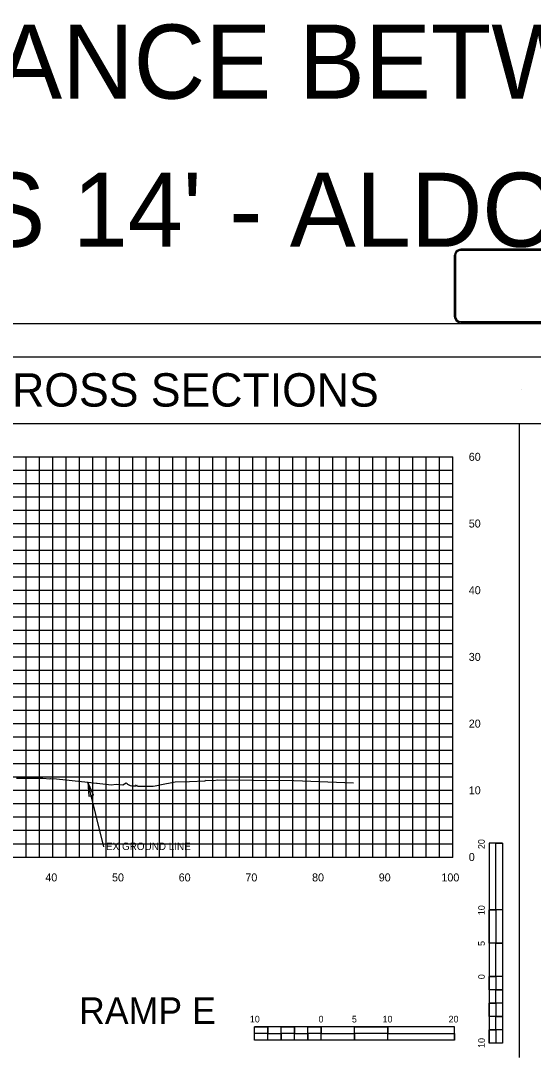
# Model space of a CAD drawing. Extents: x 2193008 to 2198143, y 1236112 to 1237864.
# Drawn here: x 2195304 to 2195380.9, y 1237228.8 to 1237383.5 of the extents above; entities that cross this region are included whole.
import ezdxf

# ---------------------------------------------------------------- set-up
doc = ezdxf.new("R2010")
doc.units = 0
for name, color, linetype in [('3', 7, 'Continuous'), ('31', 7, 'Continuous'), ('60', 7, 'Continuous'), ('ANNO-SHT', 7, 'Continuous'), ('DRAINAGE', 7, 'Continuous'), ('GSDIMS', 7, 'Continuous'), ('GSOUTLINE', 7, 'Continuous'), ('Level 1', 7, 'Continuous'), ('Level 33', 7, 'Continuous'), ('Level 55', 7, 'Continuous'), ('LIMT-CSLINE', 7, 'Continuous'), ('M-ROADS', 7, 'Continuous'), ('SHT-BNDRY', 7, 'Continuous')]:
    doc.layers.add(name, color=color, linetype=linetype)

# ---------------------------------------------------------------- blocks, each defined once
blk = doc.blocks.new('SC47208')
at = {"layer": 'Level 1'}
blk.add_line((0, 0), (0, 0), dxfattribs=at)

msp = doc.modelspace()

# ---------------------------------------------------------------- linework, layer by layer
msp.add_lwpolyline([(2195228.78, 1237133.05), (2195528.78, 1237133.05), (2195528.78, 1237323.05), (2195228.78, 1237323.05)], close=True)
at = {"layer": '3'}
for p, q in [((2195378.78, 1237228.05), (2195378.78, 1237323.05)), ((2195316.45, 1237259.66), (2195314.05, 1237269.34))]:
    msp.add_line(p, q, dxfattribs=at)
at = {"layer": '60'}
for p, q in [((2195368.78, 1237258.11), (2195368.78, 1237318.11)), ((2195368.84, 1237298.11), (2195368.78, 1237298.11)), ((2195368.84, 1237288.11), (2195368.78, 1237288.11)), ((2195368.84, 1237278.11), (2195368.78, 1237278.11)), ((2195368.84, 1237268.11), (2195368.78, 1237268.11)), ((2195238.78, 1237258.11), (2195368.78, 1237258.11)), ((2195308.78, 1237258.05), (2195308.78, 1237258.11)), ((2195318.78, 1237258.05), (2195318.78, 1237258.11)), ((2195328.78, 1237258.05), (2195328.78, 1237258.11)), ((2195338.78, 1237258.05), (2195338.78, 1237258.11)), ((2195348.78, 1237258.05), (2195348.78, 1237258.11)), ((2195358.78, 1237258.05), (2195358.78, 1237258.11)), ((2195368.78, 1237258.05), (2195368.78, 1237258.11)), ((2195368.84, 1237258.11), (2195368.78, 1237258.11))]:
    msp.add_line(p, q, dxfattribs=at)
at = {"layer": 'GSDIMS'}
msp.add_lwpolyline([(2195314.05, 1237269.34), (2195314.22, 1237267.21), (2195314.9, 1237267.39)], close=True, dxfattribs=at)
at = {"layer": 'GSOUTLINE'}
for p, q in [((2195369, 1237348.22), (2195369, 1237339.22)), ((2195369.17, 1237348.22), (2195369.17, 1237339.22)), ((2195389.5, 1237349.22), (2195370, 1237349.22)), ((2195389.5, 1237349.05), (2195370, 1237349.05)), ((2195370, 1237338.39), (2195389.5, 1237338.39)), ((2195370, 1237338.22), (2195389.5, 1237338.22))]:
    msp.add_line(p, q, dxfattribs=at)
for centre, major_axis, start_param, end_param in [((2195370, 1237348.22), (1, 0), 1.570796, 3.141593), ((2195370, 1237348.22), (0.833, 0), 1.570796, 3.141593), ((2195370, 1237339.22), (1, 0), 3.141593, 4.712389), ((2195370, 1237339.22), (0.833, 0), 3.141593, 4.712389)]:
    msp.add_ellipse(centre, major_axis=major_axis, ratio=0.999829, start_param=start_param, end_param=end_param, dxfattribs=at)
at = {"layer": 'Level 1'}
for p, q in [((2195374.26, 1237260.19), (2195374.26, 1237230.19)), ((2195376.26, 1237260.19), (2195374.26, 1237260.19)), ((2195376.26, 1237260.19), (2195376.26, 1237250.19)), ((2195376.26, 1237260.19), (2195376.26, 1237230.19)), ((2195375.26, 1237250.19), (2195374.26, 1237250.19)), ((2195376.26, 1237250.19), (2195374.26, 1237250.19)), ((2195375.26, 1237250.19), (2195375.26, 1237245.19)), ((2195376.26, 1237245.19), (2195374.26, 1237245.19)), ((2195376.26, 1237245.19), (2195375.26, 1237245.19)), ((2195376.26, 1237245.19), (2195376.26, 1237240.19)), ((2195375.26, 1237240.19), (2195374.26, 1237240.19)), ((2195376.26, 1237240.19), (2195374.26, 1237240.19)), ((2195375.26, 1237240.19), (2195375.26, 1237238.19)), ((2195376.26, 1237238.19), (2195375.26, 1237238.19)), ((2195376.26, 1237238.19), (2195376.26, 1237236.19)), ((2195375.26, 1237236.19), (2195374.26, 1237236.19)), ((2195375.26, 1237236.19), (2195375.26, 1237234.19)), ((2195376.26, 1237234.19), (2195375.26, 1237234.19)), ((2195376.26, 1237234.19), (2195376.26, 1237232.19)), ((2195369.05, 1237232.63), (2195339.05, 1237232.63)), ((2195339.05, 1237230.63), (2195339.05, 1237232.63)), ((2195341.05, 1237231.63), (2195341.05, 1237232.63)), ((2195345.05, 1237231.63), (2195345.05, 1237232.63)), ((2195349.05, 1237231.63), (2195349.05, 1237232.63)), ((2195349.05, 1237230.63), (2195349.05, 1237232.63)), ((2195354.05, 1237230.63), (2195354.05, 1237232.63)), ((2195359.05, 1237231.63), (2195359.05, 1237232.63)), ((2195359.05, 1237230.63), (2195359.05, 1237232.63)), ((2195369.05, 1237230.63), (2195369.05, 1237232.63)), ((2195375.26, 1237232.19), (2195374.26, 1237232.19)), ((2195375.26, 1237232.19), (2195375.26, 1237230.19)), ((2195341.05, 1237231.63), (2195339.05, 1237231.63)), ((2195369.05, 1237230.63), (2195339.05, 1237230.63)), ((2195343.05, 1237230.63), (2195341.05, 1237230.63)), ((2195343.05, 1237230.63), (2195343.05, 1237231.63)), ((2195345.05, 1237231.63), (2195343.05, 1237231.63)), ((2195347.05, 1237230.63), (2195345.05, 1237230.63)), ((2195347.05, 1237230.63), (2195347.05, 1237231.63)), ((2195349.05, 1237231.63), (2195347.05, 1237231.63)), ((2195354.05, 1237230.63), (2195349.05, 1237230.63)), ((2195354.05, 1237230.63), (2195354.05, 1237231.63)), ((2195359.05, 1237231.63), (2195354.05, 1237231.63)), ((2195369.05, 1237230.63), (2195359.05, 1237230.63)), ((2195376.26, 1237230.19), (2195374.26, 1237230.19))]:
    msp.add_line(p, q, dxfattribs=at)
for points in [[(2195375.26, 1237250.19), (2195375.26, 1237260.19), (2195376.26, 1237260.19), (2195376.26, 1237250.19)], [(2195374.26, 1237245.19), (2195374.26, 1237250.19), (2195375.26, 1237250.19), (2195375.26, 1237245.19)], [(2195375.26, 1237240.19), (2195375.26, 1237245.19), (2195376.26, 1237245.19), (2195376.26, 1237240.19)], [(2195374.26, 1237238.19), (2195374.26, 1237240.19), (2195375.26, 1237240.19), (2195375.26, 1237238.19)], [(2195375.26, 1237236.19), (2195375.26, 1237238.19), (2195376.26, 1237238.19), (2195376.26, 1237236.19)], [(2195374.26, 1237234.19), (2195374.26, 1237236.19), (2195375.26, 1237236.19), (2195375.26, 1237234.19)], [(2195375.26, 1237232.19), (2195375.26, 1237234.19), (2195376.26, 1237234.19), (2195376.26, 1237232.19)], [(2195339.05, 1237232.63), (2195341.05, 1237232.63), (2195341.05, 1237231.63), (2195339.05, 1237231.63)], [(2195343.05, 1237232.63), (2195345.05, 1237232.63), (2195345.05, 1237231.63), (2195343.05, 1237231.63)], [(2195347.05, 1237232.63), (2195349.05, 1237232.63), (2195349.05, 1237231.63), (2195347.05, 1237231.63)], [(2195354.05, 1237232.63), (2195359.05, 1237232.63), (2195359.05, 1237231.63), (2195354.05, 1237231.63)], [(2195374.26, 1237230.19), (2195374.26, 1237232.19), (2195375.26, 1237232.19), (2195375.26, 1237230.19)], [(2195341.05, 1237231.63), (2195343.05, 1237231.63), (2195343.05, 1237230.63), (2195341.05, 1237230.63)], [(2195345.05, 1237231.63), (2195347.05, 1237231.63), (2195347.05, 1237230.63), (2195345.05, 1237230.63)], [(2195349.05, 1237231.63), (2195354.05, 1237231.63), (2195354.05, 1237230.63), (2195349.05, 1237230.63)], [(2195359.05, 1237231.63), (2195369.05, 1237231.63), (2195369.05, 1237230.63), (2195359.05, 1237230.63)]]:
    msp.add_lwpolyline(points, close=True, dxfattribs=at)
at = {"layer": 'M-ROADS'}
for p, q in [((2195238.78, 1237318.11), (2195368.78, 1237318.11)), ((2195304.78, 1237258.11), (2195304.78, 1237318.11)), ((2195306.78, 1237258.11), (2195306.78, 1237318.11)), ((2195308.78, 1237258.11), (2195308.78, 1237318.11)), ((2195310.78, 1237258.11), (2195310.78, 1237318.11)), ((2195312.78, 1237258.11), (2195312.78, 1237318.11)), ((2195314.78, 1237258.11), (2195314.78, 1237318.11)), ((2195316.78, 1237258.11), (2195316.78, 1237318.11)), ((2195318.78, 1237258.11), (2195318.78, 1237318.11)), ((2195320.78, 1237258.11), (2195320.78, 1237318.11)), ((2195322.78, 1237258.11), (2195322.78, 1237318.11)), ((2195324.78, 1237258.11), (2195324.78, 1237318.11)), ((2195326.78, 1237258.11), (2195326.78, 1237318.11)), ((2195328.78, 1237258.11), (2195328.78, 1237318.11)), ((2195330.78, 1237258.11), (2195330.78, 1237318.11)), ((2195332.78, 1237258.11), (2195332.78, 1237318.11)), ((2195334.78, 1237258.11), (2195334.78, 1237318.11)), ((2195336.78, 1237258.11), (2195336.78, 1237318.11)), ((2195338.78, 1237258.11), (2195338.78, 1237318.11)), ((2195340.78, 1237258.11), (2195340.78, 1237318.11)), ((2195342.78, 1237258.11), (2195342.78, 1237318.11)), ((2195344.78, 1237258.11), (2195344.78, 1237318.11)), ((2195346.78, 1237258.11), (2195346.78, 1237318.11)), ((2195348.78, 1237258.11), (2195348.78, 1237318.11)), ((2195350.78, 1237258.11), (2195350.78, 1237318.11)), ((2195352.78, 1237258.11), (2195352.78, 1237318.11)), ((2195354.78, 1237258.11), (2195354.78, 1237318.11)), ((2195356.78, 1237258.11), (2195356.78, 1237318.11)), ((2195358.78, 1237258.11), (2195358.78, 1237318.11)), ((2195360.78, 1237258.11), (2195360.78, 1237318.11)), ((2195362.78, 1237258.11), (2195362.78, 1237318.11)), ((2195364.78, 1237258.11), (2195364.78, 1237318.11)), ((2195366.78, 1237258.11), (2195366.78, 1237318.11)), ((2195368.78, 1237258.11), (2195368.78, 1237318.11)), ((2195238.78, 1237316.11), (2195368.78, 1237316.11)), ((2195238.78, 1237314.11), (2195368.78, 1237314.11)), ((2195238.78, 1237312.11), (2195368.78, 1237312.11)), ((2195238.78, 1237310.11), (2195368.78, 1237310.11)), ((2195238.78, 1237308.11), (2195368.78, 1237308.11)), ((2195238.78, 1237306.11), (2195368.78, 1237306.11)), ((2195238.78, 1237304.11), (2195368.78, 1237304.11)), ((2195238.78, 1237302.11), (2195368.78, 1237302.11)), ((2195238.78, 1237300.11), (2195368.78, 1237300.11)), ((2195238.78, 1237298.11), (2195368.78, 1237298.11)), ((2195238.78, 1237296.11), (2195368.78, 1237296.11)), ((2195238.78, 1237294.11), (2195368.78, 1237294.11)), ((2195238.78, 1237292.11), (2195368.78, 1237292.11)), ((2195238.78, 1237290.11), (2195368.78, 1237290.11)), ((2195238.78, 1237288.11), (2195368.78, 1237288.11)), ((2195238.78, 1237286.11), (2195368.78, 1237286.11)), ((2195238.78, 1237284.11), (2195368.78, 1237284.11)), ((2195238.78, 1237282.11), (2195368.78, 1237282.11)), ((2195238.78, 1237280.11), (2195368.78, 1237280.11)), ((2195238.78, 1237278.11), (2195368.78, 1237278.11)), ((2195238.78, 1237276.11), (2195368.78, 1237276.11)), ((2195238.78, 1237274.11), (2195368.78, 1237274.11)), ((2195238.78, 1237272.11), (2195368.78, 1237272.11)), ((2195238.78, 1237270.11), (2195368.78, 1237270.11)), ((2195238.78, 1237268.11), (2195368.78, 1237268.11)), ((2195238.78, 1237266.11), (2195368.78, 1237266.11)), ((2195238.78, 1237264.11), (2195368.78, 1237264.11)), ((2195238.78, 1237262.11), (2195368.78, 1237262.11)), ((2195238.78, 1237260.11), (2195368.78, 1237260.11)), ((2195238.78, 1237258.11), (2195368.78, 1237258.11))]:
    msp.add_line(p, q, dxfattribs=at)
msp.add_lwpolyline([(2195203.79, 1237118.04), (2195543.79, 1237118.04), (2195543.79, 1237338.04), (2195203.79, 1237338.04)], close=True, dxfattribs=at)
msp.add_lwpolyline([(2195303.34, 1237269.95), (2195304.19, 1237269.94), (2195305.98, 1237269.92), (2195306.81, 1237269.93), (2195307.3, 1237269.92), (2195308.34, 1237269.83), (2195308.5, 1237269.87), (2195309.34, 1237269.84), (2195314.05, 1237269.34), (2195315.35, 1237269.19), (2195315.45, 1237269.19), (2195317.54, 1237268.94), (2195318.28, 1237269.02), (2195319.31, 1237268.94), (2195319.78, 1237269.24), (2195319.97, 1237269.12), (2195320.02, 1237269.03), (2195320.38, 1237268.81), (2195320.65, 1237268.78), (2195321.25, 1237268.77), (2195321.26, 1237268.77), (2195321.26, 1237268.78), (2195321.37, 1237268.94), (2195321.41, 1237268.78), (2195321.57, 1237268.74), (2195322.15, 1237268.74), (2195323.85, 1237268.74), (2195324.69, 1237268.9), (2195324.83, 1237268.92), (2195327.17, 1237269.39), (2195329.31, 1237269.44), (2195331.63, 1237269.52), (2195331.7, 1237269.62), (2195332.92, 1237269.6), (2195333.56, 1237269.69), (2195338.88, 1237269.62), (2195344.94, 1237269.56), (2195353.88, 1237269.22)], dxfattribs=at)
at = {"layer": 'SHT-BNDRY'}
msp.add_lwpolyline([(2195216.29, 1237123.04), (2195538.79, 1237123.04), (2195538.79, 1237333.04), (2195216.29, 1237333.04)], close=True, dxfattribs=at)

# ---------------------------------------------------------------- block references
at = {"layer": 'DRAINAGE', "xscale": 0.20000000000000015, "yscale": 0.20000000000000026, "rotation": -116.41666666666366}
msp.add_blockref('SC47208', (2195379.1, 1237328.23), dxfattribs=at)
msp.add_blockref('SC47208', (2195379.1, 1237328.23), dxfattribs=at)

# ---------------------------------------------------------------- texts
at = {"layer": '31'}
for s, p in [('60', (2195371.18, 1237317.51)), ('50', (2195371.18, 1237307.51)), ('40', (2195371.18, 1237297.51)), ('30', (2195371.18, 1237287.51)), ('20', (2195371.18, 1237277.51)), ('10', (2195371.18, 1237267.51)), ('0', (2195371.18, 1237257.51))]:
    msp.add_text(s, height=1.2, dxfattribs=at).set_placement(p)
at = {"layer": 'ANNO-SHT'}
msp.add_text('              SIGN CROSS SECTIONS               ', height=4.9995, rotation=360, dxfattribs=at).set_placement((2195253.66, 1237325.64))
at = {"layer": 'Level 1'}
for s, height, rotation, p in [('20', 0.999, 90.0572, (2195373.58, 1237259.3)), ('10', 0.999, 90.0572, (2195373.58, 1237249.39)), ('5', 1, 90.0572, (2195373.58, 1237244.78)), ('0', 1, 90.0572, (2195373.58, 1237239.79)), ('10', 0.999, 0.0572, (2195338.35, 1237233.3)), ('0', 1, 0.0572, (2195348.65, 1237233.3)), ('5', 0.999, 0.0572, (2195353.65, 1237233.3)), ('10', 0.999, 0.0572, (2195358.25, 1237233.3)), ('20', 0.999, 0.0572, (2195368.15, 1237233.3)), ('10', 0.999, 90.0572, (2195373.58, 1237229.49))]:
    msp.add_text(s, height=height, rotation=rotation, dxfattribs=at).set_placement(p)
at = {"layer": 'Level 33'}
msp.add_text('RAMP E', height=3.998, rotation=360, dxfattribs=at).set_placement((2195312.74, 1237233.07))
at = {"layer": 'Level 55'}
for s, height, p in [('2) SPECIAL DESIGN POSTS ARE NEEDED BECAUSE THE DISTANCE BETWEEN THE BOTTOM OF THE CENTER', 11.1046, (2194857.18, 1237371.81)), ("  OF THE SIGN AND TOP OF THE EXISTING GROUND EXCEEDS 14' - ALDOT 1202", 11.1046, (2194857.18, 1237349.6)), ('EX GROUND LINE', 1.1105, (2195316.78, 1237259.16))]:
    msp.add_text(s, height=height, dxfattribs=at).set_placement(p)
at = {"layer": 'LIMT-CSLINE'}
for s, p in [('40', (2195307.68, 1237254.45)), ('50', (2195317.68, 1237254.45)), ('60', (2195327.68, 1237254.45)), ('70', (2195337.68, 1237254.45)), ('80', (2195347.68, 1237254.45)), ('90', (2195357.68, 1237254.45)), ('100', (2195367.08, 1237254.45))]:
    msp.add_text(s, height=1.2, dxfattribs=at).set_placement(p)

doc.saveas('drawing.dxf')
